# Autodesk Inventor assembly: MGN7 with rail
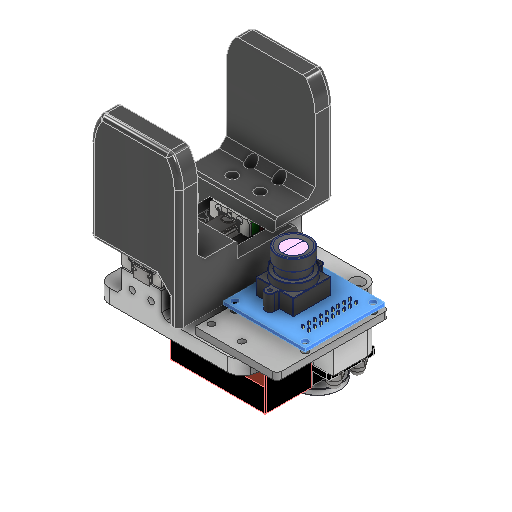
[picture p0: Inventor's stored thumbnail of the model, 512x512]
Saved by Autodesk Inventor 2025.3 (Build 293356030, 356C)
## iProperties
Created: 2019-04
Part Number: MGN7 with rail
Description: STEP AP203
Document SubType Name: Assembly
Designer: R5800u
Sending System: SolidWorks 2018
Preprocessor: SwSTEP 2.0
Title: MGN7 with rail.STEP
Revision Number: ANY
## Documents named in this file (14)
- C:\Users\R5800u\Desktop\gripper MGN7C small\gripper MGN7 small.iam
- C:\Users\R5800u\Desktop\gripper MGN7C small\MGN7 rail_100 mm.ipt
- C:\Users\R5800u\Desktop\gripper MGN7C small\MGN7C_MGN7C.ipt
- C:\Users\R5800u\Desktop\gripper MGN7C small\pignone.ipt
- C:\Users\R5800u\Desktop\gripper MGN7C small\cremagliera.ipt
- C:\Users\R5800u\Desktop\gripper MGN7C small\cremagliera2.ipt
- C:\Users\R5800u\Desktop\gripper MGN7C small\TD-9512MG v1.ipt
- C:\Users\R5800u\Desktop\gripper MGN7C small\disco_servo.ipt
- C:\Users\R5800u\Desktop\gripper MGN7C small\blocco_guida.ipt
- C:\Users\R5800u\Documents\Inventor\Content Center Files\R2025\it-IT\AS 1420\AS 1420 - 1973 - M3 x 12.ipt
- C:\Users\R5800u\Documents\Inventor\Content Center Files\R2025\it-IT\ANSI B18.3.1M(6)\ANSI B18.3.1M - M3x0,5 x 25(1).ipt
- C:\Users\R5800u\Documents\Inventor\Content Center Files\R2025\it-IT\UNI 5721\UN 5721 - M3 - 0,5.ipt
- C:\Users\R5800u\Desktop\gripper MGN7C small\Camera OV7670\Camera OV7670\Camera OV7670.ipt
- C:\Users\R5800u\Desktop\gripper MGN7C small\piastra_camera.ipt
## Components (29 placed, 14 different names)
1. MGN7 rail_100 mm_1
2. MGN7C_MGN7C_2 — Coincidente:6, Scorrevole:1, Allineato:4
3. MGN7C_MGN7C:2 — Coincidente:6, Scorrevole:2, Allineato:3
4. cremagliera2:1 — Allineato:2, Tangente:1, Angolo:2, Allineato:7
5. pignone:1 — Coincidente:7, Allineato:2, Coincidente:8, Tangente:1, Coincidente:10, Tangente:2
6. TD-9512MG v1:1
7. disco_servo:1 — Rotazionale:1, Coincidente:10
8. cremagliera:2 — Allineato:7, Tangente:2, Coincidente:30
9. disco_servo:2 — Coincidente:12
10. blocco_guida:1
11. TD-9512MG v1:2
12. AS 1420 - Metrico M3 x 12:1
13. AS 1420 - Metrico M3 x 12:4
14. AS 1420 - Metrico M3 x 12:5
15. AS 1420 - Metrico M3 x 12:7
16. Vite forgiata a testa incassata - Metrico M3x0,5 x 25:1
17. Vite forgiata a testa incassata - Metrico M3x0,5 x 25:2
18. Vite forgiata a testa incassata - Metrico M3x0,5 x 25:3
19. Vite forgiata a testa incassata - Metrico M3x0,5 x 25:4
20. UNI 5721 M3:1 — Coincidente:14
21. UNI 5721 M3:2 — Coincidente:16
22. UNI 5721 M3:3 — Coincidente:18
23. UNI 5721 M3:4 — Coincidente:20
24. UNI 5721 M3:5 — Coincidente:22
25. UNI 5721 M3:6 — Coincidente:24
26. UNI 5721 M3:7 — Coincidente:26
27. UNI 5721 M3:8 — Coincidente:28
28. Camera OV7670:1 — Coincidente:29, Allineato:11, Coincidente:30
29. piastra_camera:1 — Allineato:12, Allineato:13
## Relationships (28: Mate 15, Flush 7, TranslationJoint 2, Tangent 2, Angle 1, RevoluteJoint 1)
- Coincidente:6 [Mate]: MGN7C_MGN7C_2 ↔ MGN7C_MGN7C:2
- Scorrevole:1 [TranslationJoint]: MGN7C_MGN7C_2
- Scorrevole:2 [TranslationJoint]: MGN7C_MGN7C:2
- Coincidente:7 [Mate]: pignone:1
- Allineato:2 [Flush]: cremagliera2:1 ↔ pignone:1
- Coincidente:8 [Mate]: pignone:1
- Tangente:1: cremagliera2:1 ↔ pignone:1
- Angolo:2 [Angle]: cremagliera2:1
- Rotazionale:1 [RevoluteJoint]: disco_servo:1
- Coincidente:10 [Mate]: pignone:1 ↔ disco_servo:1
- Allineato:3 [Flush]: MGN7C_MGN7C:2
- Allineato:4 [Flush]: MGN7C_MGN7C_2
- Allineato:7 [Flush]: cremagliera2:1 ↔ cremagliera:2
- Tangente:2: pignone:1 ↔ cremagliera:2
- Coincidente:12 [Mate]: disco_servo:2
- Coincidente:14 [Mate]: UNI 5721 M3:1
- Coincidente:16 [Mate]: UNI 5721 M3:2
- Coincidente:18 [Mate]: UNI 5721 M3:3
- Coincidente:20 [Mate]: UNI 5721 M3:4
- Coincidente:22 [Mate]: UNI 5721 M3:5
- Coincidente:24 [Mate]: UNI 5721 M3:6
- Coincidente:26 [Mate]: UNI 5721 M3:7
- Coincidente:28 [Mate]: UNI 5721 M3:8
- Coincidente:29 [Mate]: Camera OV7670:1
- Allineato:11 [Flush]: Camera OV7670:1
- Coincidente:30 [Mate]: cremagliera:2 ↔ Camera OV7670:1
- Allineato:12 [Flush]: piastra_camera:1
- Allineato:13 [Flush]: piastra_camera:1
